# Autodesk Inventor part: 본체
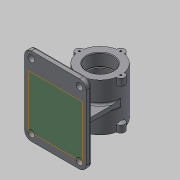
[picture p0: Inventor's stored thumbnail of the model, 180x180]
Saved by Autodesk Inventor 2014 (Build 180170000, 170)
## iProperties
Created: 2015-12
Part Number: 본체
Material: Generic
Document SubType Name: Modeling
Designer: user
Density: 1 g/cm^3
Appearance: Default
Mass: 427.214 g
Surface Area: 819.667 cm^2
Volume: 427.214 cm^3
Author: user
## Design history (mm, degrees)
sketch "Sketch11"
  geometry: C1 r 37 at (0, 0); 1 further point
  constraints: 1 centre point, 1 coincident
  dimensions: "d43" = 74 diameter of C1
extrude "Extrusion3" new body sketch "Sketch11" stored distance "d44" = 85; taper "d45" = 0 deg
sketch "Sketch12"
  geometry: L1 (37, -42.5)-(37, 42.5) reference; L2 (37, 42.5)-(37, 27.5); L3 (37, 42.5)-(44, 42.5); L4 (44, 42.5)-(44, 30.048); L5 (37, 27.5)-(44, 30.048); 1 further point
  constraints: 8 end point, 2 perpendicular, 1 point on line
  dimensions: "d46" = 15 distance of L1.end L2.end; "d47" = 7 distance of L1.end L3.end; "d48" = 70 deg angle of L2 L5
revolve "Revolution3" sketch "Sketch12" stored, may be unused: angle "d49" = 90 deg
pattern_circular "Circular Pattern2" dims angle "d51" = 360 deg
mirror "Mirror2"
workplane "Work Plane3"
sketch "Sketch14"
  geometry: L1 (55, -60)-(-55, -60); L2 (-55, -60)-(-55, 80); L3 (-55, 80)-(55, 80); L4 (55, 80)-(55, -60); 1 further point
  constraints: 8 end point, 2 parallel, 1 horizontal, 1 perpendicular
  dimensions: "d55" = 110 distance of L1.start L1.end; "d56" = 140 distance of L1.end L2.end; "d57" = 60 distance from line of L1 point (0, 0); "d58" = 55 distance from line of L2 point (0, 0)
extrude "Extrusion4" join sketch "Sketch14" distance "d59" = 10; taper "d60" = 0 deg
sketch "Sketch15"
  geometry: L1 (37, 0)-(37, -70); L2 (-37, 0)-(-37, -70); A1 r 37 centre (0, 0) between (6.969, -36.338) and (36.338, -6.969) reference; A2 r 37 centre (0, 0) between (-37, 0) and (37, 0); 1 further point
  constraints: 4 end point, 2 point on circle, 1 centre point, 1 coincident
feature "Rib1" sketch "Sketch15" dims "d62" = 1, "d63" = 8, "d64" = 0, "d65" = 0, "d66" = 1, "d67" = 1
sketch "Sketch17"
  geometry: L1 (-70, 18)-(-70, -25); L2 (-70, -25)-(-70, 25); L3 (0, -4)-(0, 4) reference; L4 (-70, 80)-(-70, -60) reference; L5 (-70, -25)-(-28.538, -19.909); L6 (-70, 25)-(-28.538, 19.909); L7 (-28.538, 19.909)-(-28.538, -19.909); 3 further points
  constraints: 10 end point, 2 midpoint, 1 collinear, 1 horizontal alignment, 1 parallel, 1 vertical
  dimensions: "d72" = 50 distance of L1.end L2.end; "d73" = 70 distance between parallel lines of L1 L3; "d74" = 97 deg angle of L1 L5; "d75" = 97 deg angle of L2 L6
extrude "Extrusion5" join sketch "Sketch17" stored distance "d76" = 12; taper "d77" = 0 deg
hole "Hole1" diameter "d80" = 47; stored, may be unused: countersink angle "d84" = 90 deg, drill point angle "d86" = 0 deg; dims "d78" = 10, "d79" = 10, "d81" = 6, "d82" = 4, "d83" = 2, "d85" = 22
sketch "Sketch18"
  geometry: C1 r 21 at (0, 0); 1 further point
  constraints: 1 centre point, 1 coincident
  dimensions: "d87" = 42 diameter of C1
extrude "Extrusion6" cut sketch "Sketch18" distance "d88" = 20.5; taper "d89" = 0 deg
mirror "Mirror3"
fillet "Fillet1" dims "d90" = 12
hole "Hole2" diameter "d93" = 12; stored, may be unused: countersink angle "d97" = 90 deg, drill point angle "d99" = 0 deg; dims "d91" = 10, "d92" = 10, "d94" = 6, "d95" = 4, "d96" = 2, "d98" = 22
pattern_linear "Rectangular Pattern1" dims "d102" = 116, "d105" = 86
sketch "Sketch19"
  geometry: A1 r 7 centre (37, 0) between (36.338, -6.969) and (36.338, 6.969) reference
hole "Hole3" sketch "Sketch19" at (37, 0) diameter "d106" = 3.242; stored, may be unused: countersink angle "d110" = 90 deg, drill point angle "d112" = 118 deg; dims "d107" = 9, "d108" = 4, "d109" = 2, "d111" = 11
pattern_circular "Circular Pattern3" dims angle "d114" = 360 deg
mirror "Mirror4"
chamfer "Chamfer1" distance "d116" = 1; stored, may be unused: second distance "d117" = 2, angle "d118" = 45 deg
chamfer "Chamfer2" distance "d119" = 1; stored, may be unused: second distance "d120" = 2, angle "d121" = 45 deg
fillet "Fillet2" dims "d122" = 0.3
fillet "Fillet3" dims "d123" = 3
fillet "Fillet4" dims "d124" = 3
sketch "Sketch20"
  geometry: L1 (0, 0)-(-40.2, 40.2); L2 (0, 0)-(-18, 0)
  constraints: 4 end point, 1 horizontal
  dimensions: "d125" = 45 deg angle of L2 L1
workplane "Work Plane4"
sketch "Sketch21"
  geometry: L1 (-7.476, -44.75)-(-7.476, 44.713); L2 (-7.476, 44.713)-(16.412, 44.713); L3 (16.412, 44.713)-(16.412, -44.75); L4 (16.412, -44.75)-(-7.476, -44.75); 1 further point
  constraints: 2 other
emboss "Emboss1" sketch "Sketch21" dims "d45" = 0, "d55" = 110, "d56" = 140, "d57" = 60, "d58" = 55, "d126" = 0.5, "d127" = 0
body "Solid2"
